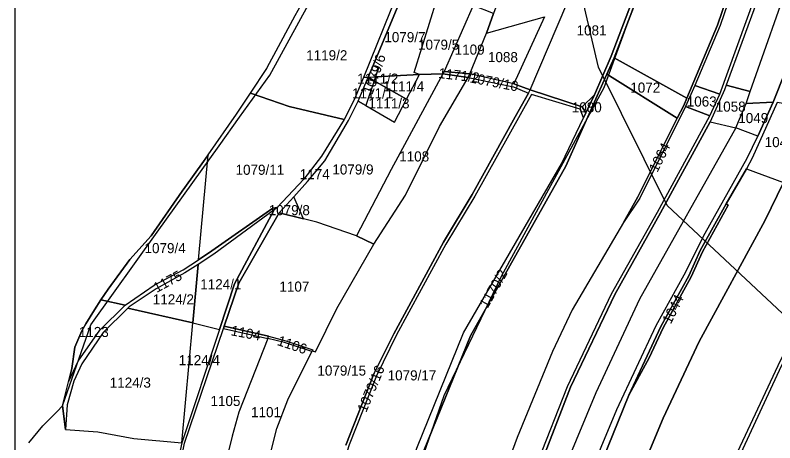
# Model space of a CAD drawing. Extents: x -623250 to -619626, y -1079612 to -1075424.
# Drawn here: x -622767 to -622013, y -1078207 to -1077782 of the extents above; entities that cross this region are included whole.
import ezdxf

# ---------------------------------------------------------------- set-up
doc = ezdxf.new("R2010")
doc.units = 0
for name, color, linetype in [('Cestní síť', 7, 'Continuous'), ('Hranice šetřená (k_ú_Lhůta)', 7, 'Continuous'), ('Hranice šetřená (k_ú_Stríhanov)', 7, 'Continuous'), ('Katastrální hranice', 7, 'Continuous'), ('Parcela nároku', 7, 'Continuous'), ('Parcelní číslo', 7, 'Continuous'), ('Pomocné k tisku', 7, 'Continuous'), ('Technická opateření liniová', 7, 'Continuous'), ('Vodní toky', 7, 'Continuous')]:
    doc.layers.add(name, color=color, linetype=linetype)

msp = doc.modelspace()

# ---------------------------------------------------------------- linework, layer by layer
at = {"layer": 'Cestní síť'}
for p, q in [((-622149.47, -1077763.68), (-622182.71, -1077854.64)), ((-622182.71, -1077854.64), (-622284.71, -1078042.01)), ((-622284.71, -1078042.01), (-622341.65, -1078160.32)), ((-622341.65, -1078160.32), (-622389.9, -1078298.41))]:
    msp.add_line(p, q, dxfattribs=at)
at = {"layer": 'Hranice šetřená (k_ú_Lhůta)'}
msp.add_lwpolyline([(-622720.22, -1078170.38), (-622714.42, -1078146.57), (-622711.2, -1078133.33), (-622708.18, -1078111.98), (-622701.07, -1078095.83), (-622697.17, -1078088.89), (-622688.59, -1078075.11), (-622682.29, -1078065.18), (-622674.89, -1078054.6), (-622653.35, -1078025.12), (-622632.12, -1078001.4), (-622601.32, -1077957.34), (-622598.77, -1077953.73), (-622580.37, -1077927.71), (-622575.78, -1077921.19), (-622547.42, -1077880.91), (-622533.6, -1077859.89), (-622517.45, -1077835.31), (-622516.63, -1077833.78), (-622510.42, -1077822.16), (-622489.05, -1077782.79), (-622486.15, -1077777.46)], dxfattribs=at)
at = {"layer": 'Hranice šetřená (k_ú_Stríhanov)'}
msp.add_lwpolyline([(-622720.22, -1078170.38), (-622717.48, -1078193.7), (-622685.18, -1078196.22), (-622649.51, -1078202.93), (-622601.63, -1078206.97), (-622620.26, -1078292.64), (-622627.38, -1078330.51), (-622628.46, -1078336.27), (-622576.57, -1078349.1), (-622570.02, -1078350.72), (-622535.57, -1078362.3), (-622543.92, -1078415.84)], dxfattribs=at)
at = {"layer": 'Katastrální hranice'}
for p, q in [((-622739.91, -1078190.38), (-622725.74, -1078175.99)), ((-622725.74, -1078175.99), (-622720.22, -1078170.38)), ((-622753.79, -1078207.17), (-622739.91, -1078190.38))]:
    msp.add_line(p, q, dxfattribs=at)
at = {"layer": 'Parcela nároku'}
for points in [[(-622293.05, -1077449.4), (-622301.21, -1077459.83), (-622323.2, -1077517.77), (-622358.58, -1077641.6), (-622366.86, -1077674.04), (-622378.29, -1077724.86), (-622388.03, -1077761.33), (-622421.37, -1077844.36), (-622416.61, -1077844.09), (-622411.85, -1077832.44), (-622381.22, -1077759.08), (-622372.05, -1077726.1), (-622361.08, -1077675.43), (-622351.69, -1077642.49), (-622316.95, -1077519.53), (-622293.67, -1077460.22), (-622280.96, -1077432.13), (-622266.14, -1077405.3), (-622256.39, -1077399.04), (-622276.04, -1077398.13)], [(-621926.36, -1077531.41), (-621894.96, -1077506.07), (-621893.59, -1077516.54), (-621909.33, -1077559.4), (-621930.15, -1077622.95), (-621947.29, -1077678.72), (-622002.1, -1077838.05), (-622014.23, -1077868.74), (-622041.29, -1077870.17), (-622037.24, -1077858.36), (-621995.09, -1077738.73), (-621975.15, -1077671.47)], [(-622241.44, -1077784.15), (-622272.09, -1077850.73), (-622255.8, -1077856.73), (-622219.47, -1077771.17), (-622200.25, -1077712.14), (-622188.37, -1077682.62), (-622185.06, -1077668.84), (-622200.38, -1077631.17), (-622189.85, -1077578.84), (-622193.8, -1077551.55), (-622188.98, -1077524.79), (-622197.86, -1077524.2), (-622209.42, -1077521.92), (-622211.22, -1077534.36), (-622200.4, -1077555.15), (-622203.93, -1077579.94), (-622221.4, -1077659.12), (-622231.95, -1077676.93), (-622262.75, -1077701.48), (-622292.03, -1077780.82), (-622299.26, -1077800.4)], [(-621996.25, -1077662.1), (-622029.85, -1077766.82), (-622061.16, -1077852.1), (-622037.24, -1077858.36), (-621995.09, -1077738.73), (-621975.15, -1077671.47), (-621926.36, -1077531.41), (-621947.59, -1077538.31), (-621962.7, -1077557.33)], [(-622044.58, -1077726.9), (-622066.91, -1077792.67), (-622092.11, -1077852.16), (-622067.31, -1077860.76), (-622032.81, -1077765.65), (-622000.97, -1077665.32), (-621969.17, -1077565.05), (-622001.57, -1077595.54), (-622006.9, -1077600.41)], [(-622103.25, -1077872.08), (-622100.21, -1077864.93), (-622069.67, -1077792.28), (-622047.02, -1077726.24), (-622010.79, -1077603.94), (-622006.9, -1077600.41), (-622044.58, -1077726.9), (-622066.91, -1077792.67), (-622092.11, -1077852.16), (-622101.46, -1077873.2), (-622146.85, -1077964.04), (-622163.05, -1077988.25), (-622148.87, -1077962.68), (-622109.83, -1077884.79)], [(-622131.56, -1077714.26), (-622010.79, -1077603.94), (-622047.02, -1077726.24), (-622069.67, -1077792.28), (-622100.21, -1077864.93), (-622172.21, -1077824.88), (-622149.94, -1077765.74)], [(-622200.25, -1077712.14), (-622188.37, -1077682.62), (-622152.3, -1077763.06), (-622175.37, -1077823), (-622191.92, -1077861.41), (-622204.05, -1077873.32), (-622255.8, -1077856.73), (-622219.47, -1077771.17)], [(-622396, -1077766.33), (-622388.03, -1077761.33), (-622421.37, -1077844.36), (-622430.71, -1077866.64), (-622440.56, -1077886.14), (-622495, -1077873.09), (-622533.6, -1077859.89), (-622517.45, -1077835.31), (-622516.63, -1077833.78), (-622510.42, -1077822.16), (-622489.05, -1077782.79), (-622486.15, -1077777.46), (-622474.63, -1077755.74), (-622469.28, -1077742.44), (-622454.93, -1077750.04), (-622432.11, -1077762.12), (-622411.26, -1077769.75)], [(-622406.36, -1077835.18), (-622409.28, -1077843.68), (-622365.85, -1077841.25), (-622371.11, -1077839.42), (-622348.3, -1077765.67), (-622381.22, -1077759.08), (-622411.85, -1077832.44)], [(-622371.11, -1077839.42), (-622348.3, -1077765.67), (-622312.32, -1077772.9), (-622341.13, -1077838.29), (-622342.38, -1077840.58), (-622365.85, -1077841.25)], [(-622312.32, -1077772.9), (-622341.13, -1077838.29), (-622315.78, -1077840.75), (-622299.26, -1077800.4), (-622292.03, -1077780.82)], [(-622315.78, -1077840.75), (-622299.26, -1077800.4), (-622241.44, -1077784.15), (-622272.09, -1077850.73)], [(-622172.21, -1077824.88), (-622100.21, -1077864.93), (-622103.25, -1077872.08), (-622109.83, -1077884.79), (-622179.57, -1077841.2)], [(-622411.85, -1077832.44), (-622416.61, -1077844.09), (-622409.28, -1077843.68), (-622406.36, -1077835.18)], [(-622365.85, -1077841.25), (-622342.38, -1077840.58), (-622393.83, -1077935.72), (-622428.32, -1078001.69), (-622467.57, -1077988), (-622480.87, -1077984.7), (-622490.61, -1077962.72), (-622476.83, -1077947.64), (-622459.79, -1077927.08), (-622436.12, -1077887.2), (-622426.55, -1077867.97), (-622419.09, -1077872.24), (-622390.46, -1077888.62), (-622378.65, -1077865.88)], [(-622342.38, -1077840.58), (-622393.83, -1077935.72), (-622428.32, -1078001.69), (-622411.01, -1078009.92), (-622379.48, -1077961.22), (-622345.71, -1077892.9), (-622317.49, -1077844.37)], [(-622416.61, -1077844.09), (-622409.28, -1077843.68), (-622410.6, -1077847.54)], [(-622409.28, -1077843.68), (-622410.6, -1077847.54), (-622378.65, -1077865.88), (-622365.85, -1077841.25)], [(-622315.78, -1077840.75), (-622341.13, -1077838.29), (-622342.38, -1077840.58), (-622317.49, -1077844.37)], [(-622272.09, -1077850.73), (-622315.78, -1077840.75), (-622317.49, -1077844.37), (-622272.38, -1077853.51), (-622257.58, -1077860.04), (-622255.8, -1077856.73)], [(-622416.61, -1077844.09), (-622410.6, -1077847.54), (-622419.09, -1077872.24), (-622426.55, -1077867.97)], [(-622410.6, -1077847.54), (-622419.09, -1077872.24), (-622390.46, -1077888.62), (-622378.65, -1077865.88)], [(-622092.11, -1077852.16), (-622101.46, -1077873.2), (-622077.24, -1077882.57), (-622067.31, -1077860.76)], [(-622062.82, -1077856.63), (-622077.11, -1077888.46), (-622051.41, -1077894.21), (-622041.29, -1077870.17), (-622037.24, -1077858.36), (-622061.16, -1077852.1)], [(-622585.22, -1078025.34), (-622575.78, -1077921.19), (-622547.42, -1077880.91), (-622533.6, -1077859.89), (-622495, -1077873.09), (-622440.56, -1077886.14), (-622463.2, -1077922.5), (-622480.65, -1077945.14), (-622507.01, -1077973.52), (-622511.29, -1077973.95), (-622571.88, -1078016.56)], [(-622408.35, -1078140.61), (-622435.7, -1078209.08), (-622452.13, -1078261.78), (-622462.62, -1078309.55), (-622474.14, -1078445.71), (-622482.98, -1078507.18), (-622442.57, -1078471.35), (-622412.18, -1078429.67), (-622403.15, -1078330.82), (-622390.69, -1078278.24), (-622368.3, -1078212.5), (-622321.87, -1078097.96), (-622224.5, -1077930.06), (-622202.82, -1077884.37), (-622206.1, -1077875.93), (-622254.59, -1077861.36), (-622310.83, -1077962.21), (-622339.7, -1078009.8), (-622388.42, -1078099.88)], [(-622204.05, -1077873.32), (-622191.92, -1077861.41), (-622200.43, -1077879.33)], [(-622051.41, -1077894.21), (-622041.29, -1077870.17), (-622014.23, -1077868.74), (-622029.61, -1077902.63)], [(-622010.54, -1077869.22), (-622035.41, -1077924.43), (-622041.01, -1077935.09), (-622004.26, -1077948.64), (-621991.43, -1077923.09), (-621971.17, -1077875.84)], [(-622575.78, -1077921.19), (-622580.37, -1077927.71), (-622598.77, -1077953.73), (-622601.32, -1077957.34), (-622632.12, -1078001.4), (-622653.35, -1078025.12), (-622674.89, -1078054.6), (-622682.29, -1078065.18), (-622658.08, -1078070.26), (-622629.19, -1078050.44), (-622600.4, -1078035.34), (-622585.22, -1078025.34)], [(-622480.87, -1077984.7), (-622490.61, -1077962.72), (-622505.17, -1077978.66)], [(-622098.16, -1078041.39), (-622086.75, -1078016.2), (-622061.18, -1077969.87), (-622059.24, -1077971.04), (-622084.67, -1078017.47), (-622095.72, -1078042.15), (-622123.75, -1078092.87), (-622137.66, -1078122.83), (-622157.77, -1078159.77), (-622125.96, -1078091.52)], [(-622714.42, -1078146.57), (-622704.88, -1078125.96), (-622683.14, -1078095.14), (-622658.08, -1078070.26), (-622629.19, -1078050.44), (-622600.4, -1078035.34), (-622585.22, -1078025.34), (-622571.88, -1078016.56), (-622511.29, -1077973.95), (-622507.01, -1077973.52), (-622510.13, -1077975.82), (-622569.98, -1078019.85), (-622585.71, -1078030), (-622598.78, -1078038.44), (-622627.3, -1078054.33), (-622654.19, -1078072.18), (-622655.55, -1078073.53), (-622679.89, -1078097.66), (-622701.22, -1078128.53), (-622709.11, -1078145.9), (-622715.54, -1078169.47), (-622717.48, -1078193.7), (-622720.22, -1078170.38)], [(-622510.13, -1077975.82), (-622569.98, -1078019.85), (-622585.71, -1078030), (-622590.93, -1078088.06), (-622564.49, -1078094.7), (-622549.5, -1078049.38)], [(-622480.87, -1077984.7), (-622505.17, -1077978.66), (-622545.23, -1078048.68), (-622559.65, -1078091.21), (-622515.61, -1078101.21), (-622498.55, -1078105.66), (-622471.52, -1078114.76), (-622472.17, -1078115.83), (-622469.11, -1078116.87), (-622447.92, -1078073.6), (-622411.01, -1078009.92), (-622428.32, -1078001.69), (-622467.57, -1077988)], [(-622654.19, -1078072.18), (-622655.55, -1078073.53), (-622590.93, -1078088.06), (-622585.71, -1078030), (-622598.78, -1078038.44), (-622627.3, -1078054.33)], [(-622658.08, -1078070.26), (-622682.29, -1078065.18), (-622688.59, -1078075.11), (-622697.17, -1078088.89), (-622701.07, -1078095.83), (-622708.18, -1078111.98), (-622711.2, -1078133.33), (-622714.42, -1078146.57), (-622704.88, -1078125.96), (-622683.14, -1078095.14)], [(-622701.22, -1078128.53), (-622709.11, -1078145.9), (-622715.54, -1078169.47), (-622717.48, -1078193.7), (-622685.18, -1078196.22), (-622649.51, -1078202.93), (-622601.63, -1078206.97), (-622590.93, -1078088.06), (-622655.55, -1078073.53), (-622679.89, -1078097.66)], [(-622601.63, -1078206.97), (-622590.93, -1078088.06), (-622564.49, -1078094.7)], [(-622515.61, -1078101.21), (-622559.65, -1078091.21), (-622560.5, -1078093.7), (-622516.4, -1078103.41)], [(-622599.04, -1078207.4), (-622560.5, -1078093.7), (-622516.4, -1078103.41), (-622545.15, -1078176.55), (-622551.88, -1078200.44), (-622561.72, -1078240.68), (-622603.17, -1078227.32)], [(-622545.15, -1078176.55), (-622551.88, -1078200.44), (-622561.72, -1078240.68), (-622562.48, -1078243.8), (-622561.05, -1078244.25), (-622522.97, -1078254.25), (-622507.36, -1078192.76), (-622496.58, -1078164.57), (-622472.53, -1078116.42), (-622499.92, -1078107.45), (-622516.4, -1078103.41)], [(-622516.4, -1078103.41), (-622515.61, -1078101.21), (-622498.55, -1078105.66), (-622471.52, -1078114.76), (-622472.17, -1078115.83), (-622472.53, -1078116.42), (-622499.92, -1078107.45)]]:
    msp.add_lwpolyline(points, close=True, dxfattribs=at)
for points in [[(-622248.12, -1078225.94), (-622218.78, -1078151.19), (-622175.12, -1078059.04), (-622129.3, -1077977.94), (-622077.24, -1077882.57), (-622067.31, -1077860.76), (-622032.81, -1077765.65), (-622000.97, -1077665.32), (-621969.17, -1077565.05), (-621962.7, -1077557.33), (-621996.25, -1077662.1), (-622029.85, -1077766.82), (-622061.16, -1077852.1), (-622062.82, -1077856.63), (-622077.11, -1077888.46), (-622126.3, -1077978.66), (-622171.76, -1078059.87), (-622215.62, -1078151.71), (-622244.99, -1078227.38)], [(-622059.07, -1078244.77), (-622006.23, -1078130.73), (-621991.41, -1078102.15), (-621908.84, -1077952.82), (-621870.37, -1077892.96), (-621848.84, -1077819.93), (-621826.8, -1077755.86), (-621795.11, -1077653.4), (-621798.63, -1077652.31), (-621831.36, -1077755), (-621853.49, -1077819.24), (-621874.93, -1077892.1), (-621914.84, -1077955.44), (-621995.11, -1078100.43), (-622009.77, -1078130.49), (-622062.34, -1078242.79)], [(-622368.3, -1078212.5), (-622321.87, -1078097.96), (-622224.5, -1077930.06), (-622202.82, -1077884.37), (-622200.43, -1077879.33), (-622191.92, -1077861.41), (-622175.37, -1077823), (-622152.3, -1077763.06)], [(-622149.94, -1077765.74), (-622172.21, -1077824.88), (-622179.57, -1077841.2), (-622220.34, -1077932.34), (-622315.19, -1078100.94), (-622361.04, -1078213.95)], [(-622361.04, -1078213.95), (-622315.19, -1078100.94), (-622220.34, -1077932.34), (-622179.57, -1077841.2), (-622109.83, -1077884.79), (-622148.87, -1077962.68), (-622163.05, -1077988.25), (-622213.98, -1078075.06), (-622233.56, -1078116.49), (-622268.65, -1078201.83), (-622291.9, -1078264.56)], [(-622218.08, -1078290.15), (-622169.57, -1078173.85), (-622130.48, -1078090.46), (-622102.75, -1078040.22), (-622082.09, -1077998.88), (-622040.22, -1077924.29), (-622029.61, -1077902.63), (-622014.23, -1077868.74), (-622002.1, -1077838.05)], [(-622599.04, -1078207.4), (-622560.5, -1078093.7), (-622559.65, -1078091.21), (-622545.23, -1078048.68), (-622505.17, -1077978.66), (-622490.61, -1077962.72), (-622476.83, -1077947.64), (-622459.79, -1077927.08), (-622436.12, -1077887.2), (-622426.55, -1077867.97), (-622416.61, -1077844.09), (-622421.37, -1077844.36), (-622430.71, -1077866.64), (-622440.56, -1077886.14), (-622463.2, -1077922.5), (-622480.65, -1077945.14), (-622507.01, -1077973.52), (-622510.13, -1077975.82), (-622549.5, -1078049.38), (-622564.49, -1078094.7), (-622601.63, -1078206.97), (-622620.26, -1078292.64)], [(-622522.97, -1078254.25), (-622507.36, -1078192.76), (-622496.58, -1078164.57), (-622472.53, -1078116.42), (-622472.17, -1078115.83), (-622469.11, -1078116.87), (-622447.92, -1078073.6), (-622411.01, -1078009.92), (-622379.48, -1077961.22), (-622345.71, -1077892.9), (-622317.49, -1077844.37), (-622272.38, -1077853.51), (-622257.58, -1077860.04), (-622270.52, -1077883.45), (-622313.28, -1077960.63), (-622341.78, -1078007.98), (-622391.08, -1078098.76), (-622410.71, -1078138), (-622438.97, -1078209.28)], [(-622438.97, -1078209.28), (-622410.71, -1078138), (-622391.08, -1078098.76), (-622341.78, -1078007.98), (-622313.28, -1077960.63), (-622270.52, -1077883.45), (-622257.58, -1077860.04), (-622255.8, -1077856.73), (-622204.05, -1077873.32), (-622200.43, -1077879.33), (-622202.82, -1077884.37), (-622206.1, -1077875.93), (-622254.59, -1077861.36), (-622310.83, -1077962.21), (-622339.7, -1078009.8), (-622388.42, -1078099.88), (-622408.35, -1078140.61), (-622435.7, -1078209.08)], [(-622248.12, -1078225.94), (-622218.78, -1078151.19), (-622175.12, -1078059.04), (-622129.3, -1077977.94), (-622077.24, -1077882.57), (-622101.46, -1077873.2), (-622146.85, -1077964.04), (-622163.05, -1077988.25), (-622213.98, -1078075.06), (-622233.56, -1078116.49), (-622268.65, -1078201.83), (-622291.9, -1078264.56)], [(-622010.54, -1077869.22), (-622035.41, -1077924.43), (-622041.01, -1077935.09), (-622061.18, -1077969.87), (-622086.75, -1078016.2), (-622098.16, -1078041.39), (-622125.96, -1078091.52), (-622157.77, -1078159.77), (-622210.19, -1078288.9)], [(-622244.99, -1078227.38), (-622215.62, -1078151.71), (-622171.76, -1078059.87), (-622126.3, -1077978.66), (-622077.11, -1077888.46), (-622051.41, -1077894.21), (-622147.02, -1078064.43), (-622190.56, -1078157.3), (-622218.93, -1078226.05)], [(-622218.08, -1078290.15), (-622169.57, -1078173.85), (-622130.48, -1078090.46), (-622102.75, -1078040.22), (-622082.09, -1077998.88), (-622040.22, -1077924.29), (-622029.61, -1077902.63), (-622051.41, -1077894.21), (-622147.02, -1078064.43), (-622190.56, -1078157.3), (-622218.93, -1078226.05)], [(-622164.43, -1078280.38), (-622123.52, -1078182.67), (-622088, -1078106.41), (-622022.63, -1077986.57), (-622004.26, -1077948.64), (-621991.43, -1077923.09), (-621914.84, -1077955.44), (-621995.11, -1078100.43), (-622009.77, -1078130.49), (-622062.34, -1078242.79)], [(-622210.19, -1078288.9), (-622157.77, -1078159.77), (-622137.66, -1078122.83), (-622123.75, -1078092.87), (-622095.72, -1078042.15), (-622084.67, -1078017.47), (-622059.24, -1077971.04), (-622061.18, -1077969.87), (-622041.01, -1077935.09), (-622004.26, -1077948.64), (-622022.63, -1077986.57), (-622088, -1078106.41), (-622123.52, -1078182.67), (-622164.43, -1078280.38)], [(-622059.07, -1078244.77), (-622006.23, -1078130.73), (-621991.41, -1078102.15), (-621908.84, -1077952.82), (-621899.15, -1077958.64), (-621887.93, -1077940.66), (-621838.56, -1077956.15), (-621845.42, -1077973.2), (-621836.94, -1077988.14), (-621840.44, -1077996.77), (-621878.07, -1078067.41), (-621920.88, -1078143.42), (-621992.93, -1078299.5)]]:
    msp.add_lwpolyline(points, dxfattribs=at)
at = {"layer": 'Pomocné k tisku'}
msp.add_lwpolyline([(-622767.31, -1075424.03), (-619626.32, -1075424.03), (-619626.32, -1079239.36), (-622767.31, -1079239.36)], close=True, dxfattribs=at)
at = {"layer": 'Technická opateření liniová'}
for p, q in [((-622187.91, -1077833.95), (-622204.51, -1077762.92)), ((-622119.57, -1077971.37), (-622187.91, -1077833.95)), ((-621844.2, -1078229.72), (-622119.57, -1077971.37))]:
    msp.add_line(p, q, dxfattribs=at)
at = {"layer": 'Vodní toky'}
for p, q in [((-622514.52, -1077842), (-622476.11, -1077771.91)), ((-622544.45, -1077883.81), (-622514.52, -1077842)), ((-622564.72, -1077912.12), (-622544.45, -1077883.81)), ((-622626.12, -1077997.88), (-622564.72, -1077912.12)), ((-622692.14, -1078090.09), (-622626.12, -1077997.88)), ((-622720.22, -1078170.38), (-622692.14, -1078090.09))]:
    msp.add_line(p, q, dxfattribs=at)

# ---------------------------------------------------------------- texts
at = {"layer": 'Parcelní číslo'}
for s, p in [('1079/7', (-622400.62, -1077809.27)), ('1081', (-622209.66, -1077802.55)), ('1079/5', (-622367.13, -1077816.75)), ('1109', (-622330.76, -1077821.65)), ('1119/2', (-622478.25, -1077827.26)), ('1088', (-622297.71, -1077829.09)), ('1111/2', (-622427.64, -1077850.47)), ('1111/4', (-622401.9, -1077858.09)), ('1072', (-622156.33, -1077859.38)), ('1111/1', (-622432.66, -1077865.07)), ('1111/3', (-622416.5, -1077875.03)), ('1063', (-622100.23, -1077873.19)), ('1080', (-622214.42, -1077878.95)), ('1058', (-622071.45, -1077878.25)), ('1049', (-622049.04, -1077889.59)), ('1042', (-622022.83, -1077913.5)), ('1108', (-622385.84, -1077927.72)), ('1079/11', (-622548.42, -1077940.96)), ('1079/9', (-622452.25, -1077940.64)), ('1174', (-622484.64, -1077945.34)), ('1079/8', (-622515.51, -1077981.06)), ('1079/4', (-622638.83, -1078018.76)), ('1124/1', (-622583.49, -1078054.63)), ('1107', (-622504.87, -1078056.95)), ('1124/2', (-622630.64, -1078069.61)), ('1123', (-622704.11, -1078102.02)), ('1124/4', (-622604.83, -1078129.99)), ('1079/15', (-622467.11, -1078140.34)), ('1079/17', (-622397.35, -1078145.1)), ('1124/3', (-622673.41, -1078152.32)), ('1105', (-622573.32, -1078170.56)), ('1101', (-622533, -1078181.65))]:
    msp.add_text(s, height=10, dxfattribs=at).set_placement(p)
for s, rotation, p in [('1079/6', 70.59267, (-622412.56, -1077861.94)), ('1171/2', 353.25207, (-622347.4, -1077844.81)), ('1079/10', 349.07238, (-622316.17, -1077849.15)), ('1064', 63.62946, (-622129.38, -1077939.12)), ('1175', 28.21734, (-622626.74, -1078058.3)), ('1170/2', 60.37623, (-622298.11, -1078074.23)), ('1044', 63.33705, (-622116.14, -1078089.82)), ('1104', 349.02432, (-622553.67, -1078100.17)), ('1106', 341.3862, (-622507.78, -1078109.79)), ('1079/16', 67.31658, (-622418.66, -1078177.55))]:
    msp.add_text(s, height=10, rotation=rotation, dxfattribs=at).set_placement(p)

doc.saveas('drawing.dxf')
